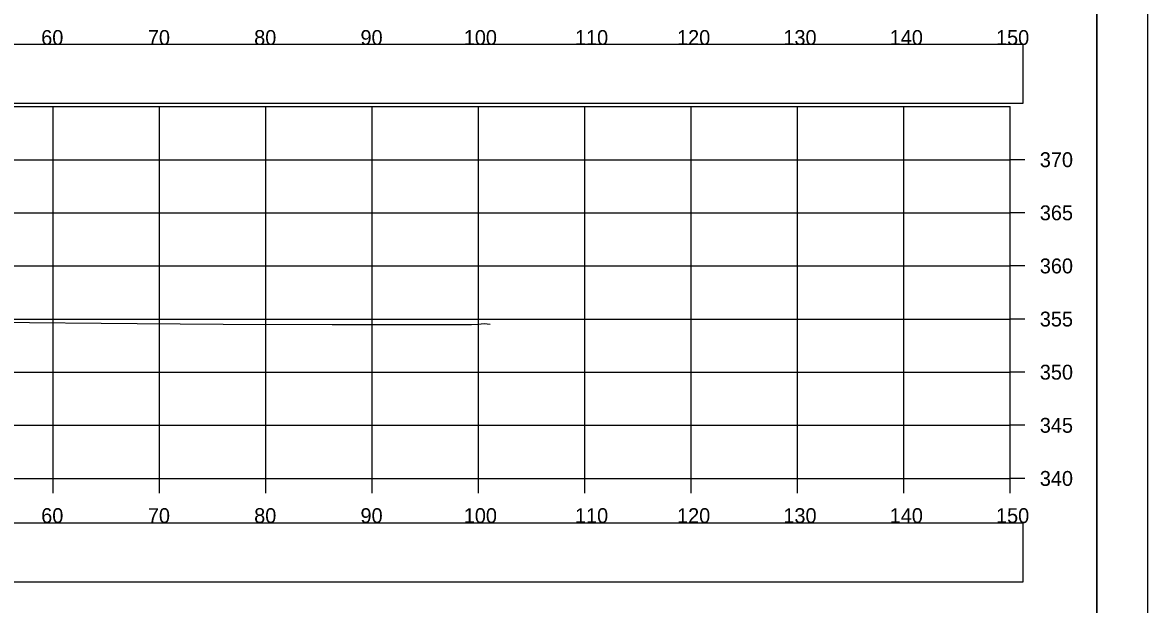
# Model space of a CAD drawing. Extents: x 1376273 to 1384221, y 378927 to 384592.
# Drawn here: x 1377114.9 to 1377220.7, y 382774 to 382828.8 of the extents above; entities that cross this region are included whole.
import ezdxf

# ---------------------------------------------------------------- set-up
doc = ezdxf.new("R2010")
doc.units = 0
for name, color, linetype in [('R_Axis', 7, 'Continuous'), ('R_Axis Annot', 7, 'Continuous'), ('R_Border', 7, 'Continuous'), ('R_Exist Surface', 7, 'Continuous'), ('R_Grid', 7, 'Continuous'), ('R_No Plot', 7, 'Continuous')]:
    doc.layers.add(name, color=color, linetype=linetype)

msp = doc.modelspace()

# ---------------------------------------------------------------- linework, layer by layer
at = {"layer": 'R_Axis'}
for p, q in [((1377207.77, 382785.87), (1377207.77, 382815.87)), ((1377209.17, 382815.87), (1377207.77, 382815.87)), ((1377209.17, 382810.87), (1377207.77, 382810.87)), ((1377209.17, 382805.87), (1377207.77, 382805.87)), ((1377209.17, 382800.87), (1377207.77, 382800.87)), ((1377209.17, 382795.87), (1377207.77, 382795.87)), ((1377209.17, 382790.87), (1377207.77, 382790.87)), ((1376907.77, 382785.87), (1377207.77, 382785.87)), ((1377117.77, 382784.47), (1377117.77, 382785.87)), ((1377127.77, 382784.47), (1377127.77, 382785.87)), ((1377137.77, 382784.47), (1377137.77, 382785.87)), ((1377147.77, 382784.47), (1377147.77, 382785.87)), ((1377157.77, 382784.47), (1377157.77, 382785.87)), ((1377167.77, 382784.47), (1377167.77, 382785.87)), ((1377177.77, 382784.47), (1377177.77, 382785.87)), ((1377187.77, 382784.47), (1377187.77, 382785.87)), ((1377197.77, 382784.47), (1377197.77, 382785.87)), ((1377207.77, 382784.47), (1377207.77, 382785.87)), ((1377209.17, 382785.87), (1377207.77, 382785.87))]:
    msp.add_line(p, q, dxfattribs=at)
at = {"layer": 'R_Axis Annot'}
for points in [[(1376907.2, 382821.19), (1377209.01, 382821.19), (1377209.01, 382826.71), (1376907.2, 382826.71)], [(1376907.2, 382776.14), (1377209.01, 382776.14), (1377209.01, 382781.66), (1376907.2, 382781.66)]]:
    msp.add_lwpolyline(points, close=True, dxfattribs=at)
at = {"layer": 'R_Border'}
msp.add_line((1377215.95, 382675.87), (1377215.95, 382881.33), dxfattribs=at)
at = {"layer": 'R_Exist Surface'}
msp.add_lwpolyline([(1377112.14, 382800.59), (1377125.69, 382800.45), (1377133.77, 382800.38), (1377144, 382800.36), (1377157.11, 382800.35), (1377157.76, 382800.4), (1377158.3, 382800.44), (1377158.89, 382800.4)], dxfattribs=at)
at = {"layer": 'R_Grid'}
for p, q in [((1376907.77, 382820.87), (1377207.77, 382820.87)), ((1377117.77, 382785.87), (1377117.77, 382820.87)), ((1377127.77, 382785.87), (1377127.77, 382820.87)), ((1377137.77, 382785.87), (1377137.77, 382820.87)), ((1377147.77, 382785.87), (1377147.77, 382820.87)), ((1377157.77, 382785.87), (1377157.77, 382820.87)), ((1377167.77, 382785.87), (1377167.77, 382820.87)), ((1377177.77, 382785.87), (1377177.77, 382820.87)), ((1377187.77, 382785.87), (1377187.77, 382820.87)), ((1377197.77, 382785.87), (1377197.77, 382820.87)), ((1377207.77, 382785.87), (1377207.77, 382820.87)), ((1376907.77, 382815.87), (1377207.77, 382815.87)), ((1376907.77, 382815.87), (1377207.77, 382815.87)), ((1377117.77, 382785.87), (1377117.77, 382815.87)), ((1377127.77, 382785.87), (1377127.77, 382815.87)), ((1377137.77, 382785.87), (1377137.77, 382815.87)), ((1377147.77, 382785.87), (1377147.77, 382815.87)), ((1377157.77, 382785.87), (1377157.77, 382815.87)), ((1377167.77, 382785.87), (1377167.77, 382815.87)), ((1377177.77, 382785.87), (1377177.77, 382815.87)), ((1377187.77, 382785.87), (1377187.77, 382815.87)), ((1377197.77, 382785.87), (1377197.77, 382815.87)), ((1377207.77, 382785.87), (1377207.77, 382815.87)), ((1376907.77, 382810.87), (1377207.77, 382810.87)), ((1376907.77, 382810.87), (1377207.77, 382810.87)), ((1376907.77, 382805.87), (1377207.77, 382805.87)), ((1376907.77, 382805.87), (1377207.77, 382805.87)), ((1376907.77, 382800.87), (1377207.77, 382800.87)), ((1376907.77, 382800.87), (1377207.77, 382800.87)), ((1376907.77, 382795.87), (1377207.77, 382795.87)), ((1376907.77, 382795.87), (1377207.77, 382795.87)), ((1376907.77, 382790.87), (1377207.77, 382790.87)), ((1376907.77, 382790.87), (1377207.77, 382790.87)), ((1376907.77, 382785.87), (1377207.77, 382785.87)), ((1376907.77, 382785.87), (1377207.77, 382785.87))]:
    msp.add_line(p, q, dxfattribs=at)
at = {"layer": 'R_No Plot'}
for points in [[(1376887.36, 382885.23), (1377220.7, 382885.23), (1377220.7, 382671.89), (1376887.36, 382671.89)], [(1377133.69, 382881.33), (1377133.69, 382871.45), (1377169.42, 382871.45), (1377169.42, 382868.53), (1377192.62, 382868.53), (1377192.62, 382844.2), (1377215.95, 382844.2), (1377215.95, 382675.87), (1376899.77, 382675.87), (1376899.77, 382881.33)]]:
    msp.add_lwpolyline(points, close=True, dxfattribs=at)

# ---------------------------------------------------------------- texts
at = {"layer": 'R_Axis Annot'}
for s, p in [('60', (1377116.65, 382826.67)), ('70', (1377126.68, 382826.67)), ('80', (1377136.68, 382826.67)), ('90', (1377146.68, 382826.67)), ('100', (1377156.39, 382826.67)), ('110', (1377166.85, 382826.67)), ('120', (1377176.45, 382826.67)), ('130', (1377186.45, 382826.67)), ('140', (1377196.45, 382826.67)), ('150', (1377206.45, 382826.67)), ('370', (1377210.57, 382815.17)), ('365', (1377210.57, 382810.17)), ('360', (1377210.57, 382805.17)), ('355', (1377210.57, 382800.17)), ('350', (1377210.57, 382795.17)), ('345', (1377210.57, 382790.17)), ('340', (1377210.57, 382785.17)), ('60', (1377116.65, 382781.67)), ('70', (1377126.68, 382781.67)), ('80', (1377136.68, 382781.67)), ('90', (1377146.68, 382781.67)), ('100', (1377156.39, 382781.67)), ('110', (1377166.85, 382781.67)), ('120', (1377176.45, 382781.67)), ('130', (1377186.45, 382781.67)), ('140', (1377196.45, 382781.67)), ('150', (1377206.45, 382781.67))]:
    msp.add_text(s, height=1.4, dxfattribs=at).set_placement(p)

doc.saveas('drawing.dxf')
